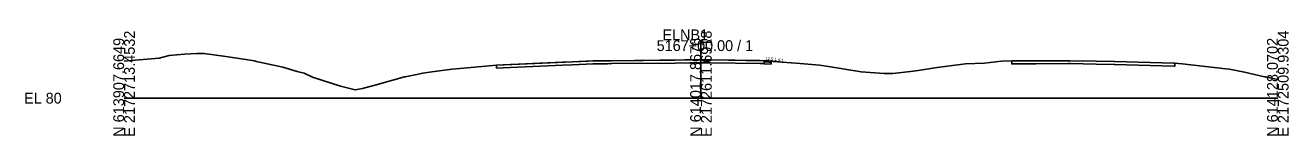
# Model space of a CAD drawing. Extents: x -26 to 1303, y -3010 to 12038.
# Drawn here: x -25.7 to 302.8, y -2509.7 to -2482.2 of the extents above; entities that cross this region are included whole.
import ezdxf

# ---------------------------------------------------------------- set-up
doc = ezdxf.new("R2010")
doc.units = 0
for name, color, linetype in [('RD_GPK_XS_Cell', 7, 'Continuous'), ('RD_XS_Base', 7, 'Continuous'), ('RD_XS_ExGround', 7, 'Continuous'), ('RD_XS_ExPaveRet', 7, 'Continuous'), ('RD_XS_Greenside', 7, 'Continuous'), ('RD_XS_Pave', 7, 'Continuous'), ('RD_XS_PaveOvlay_CP', 7, 'Continuous'), ('RD_XS_TieSlope', 7, 'Continuous'), ('RD_XS_TX_ShdSlope', 7, 'Continuous'), ('RD_XS_TX_Slope', 7, 'Continuous')]:
    doc.layers.add(name, color=color, linetype=linetype)

msp = doc.modelspace()

# ---------------------------------------------------------------- linework, layer by layer
at = {"layer": 'RD_GPK_XS_Cell'}
for p, q in [((150, -2500), (150, -2485)), ((0, -2500), (150, -2500)), ((150, -2500), (300, -2500))]:
    msp.add_line(p, q, dxfattribs=at)
at = {"layer": 'RD_XS_Base'}
for p, q in [((167.76, -2490.68), (166.41, -2490.63)), ((166.41, -2491.13), (168.26, -2491.2)), ((168.26, -2490.7), (167.76, -2490.68)), ((167.76, -2490.68), (167.76, -2490.68)), ((168.26, -2491.2), (168.26, -2490.7)), ((168.26, -2490.7), (168.26, -2490.7))]:
    msp.add_line(p, q, dxfattribs=at)
at = {"layer": 'RD_XS_ExGround'}
msp.add_lwpolyline([(0, -2490.43), (1.84, -2490.25), (9.12, -2489.69), (11.74, -2488.96), (15.67, -2488.57), (18.92, -2488.46), (20.85, -2488.4), (26.43, -2489.18), (33.88, -2490.35), (34.35, -2490.5), (35.2, -2490.65), (41.3, -2491.98), (44.99, -2493.07), (46.82, -2493.51), (48.98, -2494.57), (56.29, -2496.86), (60.13, -2497.85), (61.96, -2497.47), (65.59, -2496.51), (72.95, -2494.52), (73.13, -2494.5), (75.71, -2493.94), (77.69, -2493.5), (80.02, -2493.18), (85.31, -2492.5), (88.29, -2492.25), (92.11, -2491.87), (96.85, -2491.45), (120.67, -2490.42), (122.42, -2490.36), (123.26, -2490.31), (124.4, -2490.35), (126.24, -2490.33), (145.78, -2490.12), (150.65, -2490.07), (152.45, -2490.1), (166.42, -2490.31), (175.78, -2491.07), (180.86, -2491.49), (183.16, -2491.8), (191.64, -2493.19), (195.18, -2493.41), (197.64, -2493.64), (198.46, -2493.61), (199.93, -2493.59), (204.53, -2493.12), (206.49, -2492.85), (211.43, -2492.08), (218.76, -2491.08), (223.77, -2490.9), (228.17, -2490.46), (230.82, -2490.37), (237.11, -2490.33), (245.76, -2490.31), (252.79, -2490.45), (257.64, -2490.54), (269.83, -2490.87), (273.24, -2490.96), (275.09, -2491.09), (286.46, -2492.39), (287.48, -2492.5), (291.38, -2493.24), (296.55, -2494.46), (296.78, -2494.51), (297.02, -2494.57), (300, -2495.17)], dxfattribs=at)
at = {"layer": 'RD_XS_ExPaveRet'}
for points in [[(165.36, -2490.29), (166.41, -2490.31), (166.41, -2490.44), (166.41, -2491.06), (165.36, -2491.04), (152.45, -2490.85), (150.85, -2490.82), (150.65, -2490.82), (150.11, -2490.82), (147.01, -2490.86), (143.27, -2490.9), (126.64, -2491.07), (126.38, -2491.08), (126.09, -2491.07), (125.69, -2491.08), (125.16, -2491.1), (121.98, -2491.1), (121.95, -2491.1), (121.93, -2491.1), (116.6, -2491.37), (113.99, -2491.46), (98.57, -2492.13), (96.85, -2492.2), (96.85, -2491.58), (96.85, -2491.45), (98.57, -2491.38), (113.99, -2490.71), (116.6, -2490.62), (121.93, -2490.35), (121.95, -2490.35), (121.98, -2490.35), (125.16, -2490.35), (125.69, -2490.33), (126.09, -2490.32), (126.38, -2490.33), (126.64, -2490.32), (143.27, -2490.15), (147.01, -2490.11), (150.11, -2490.07), (150.65, -2490.07), (150.85, -2490.07), (152.45, -2490.1), (165.36, -2490.29)], [(152.45, -2490.1), (150.85, -2490.07), (150.65, -2490.07), (150.11, -2490.07), (147.01, -2490.11), (143.27, -2490.15), (126.64, -2490.32), (126.38, -2490.33), (126.09, -2490.32), (125.69, -2490.33), (125.16, -2490.35), (121.98, -2490.35), (121.95, -2490.35), (121.93, -2490.35), (116.6, -2490.62), (113.99, -2490.71), (98.57, -2491.38), (96.85, -2491.45), (96.85, -2491.58), (96.85, -2492.2), (98.57, -2492.13), (113.99, -2491.46), (116.6, -2491.37), (121.93, -2491.1), (121.95, -2491.1), (121.98, -2491.1), (125.16, -2491.1), (125.69, -2491.08), (126.09, -2491.07), (126.38, -2491.08), (126.64, -2491.07), (143.27, -2490.9), (147.01, -2490.86), (150.11, -2490.82), (150.65, -2490.82), (150.85, -2490.82), (152.45, -2490.85), (165.36, -2491.04), (166.41, -2491.06), (166.41, -2490.44), (166.41, -2490.31), (165.36, -2490.29), (152.45, -2490.1)], [(273.24, -2490.96), (272.98, -2490.96), (269.83, -2490.87), (260.63, -2490.62), (257.64, -2490.54), (257.41, -2490.54), (252.79, -2490.45), (246, -2490.32), (245.86, -2490.32), (245.76, -2490.31), (245.75, -2490.31), (245.65, -2490.31), (245.53, -2490.31), (237.11, -2490.33), (231.27, -2490.37), (230.82, -2490.37), (230.82, -2490.82), (230.82, -2491.12), (231.27, -2491.12), (237.11, -2491.08), (245.53, -2491.06), (245.65, -2491.06), (245.75, -2491.06), (245.76, -2491.06), (245.86, -2491.07), (246, -2491.07), (252.79, -2491.2), (257.41, -2491.29), (257.64, -2491.29), (260.63, -2491.37), (269.83, -2491.62), (272.98, -2491.71), (273.24, -2491.71), (273.24, -2491.71), (273.24, -2491.71), (273.24, -2491.26), (273.24, -2490.96), (273.24, -2490.96), (273.24, -2490.96)], [(273.24, -2490.96), (272.98, -2490.96), (269.83, -2490.87), (260.63, -2490.62), (257.64, -2490.54), (257.41, -2490.54), (252.79, -2490.45), (246, -2490.32), (245.86, -2490.32), (245.76, -2490.31), (245.75, -2490.31), (245.65, -2490.31), (245.53, -2490.31), (237.11, -2490.33), (231.27, -2490.37), (230.82, -2490.37), (230.82, -2490.82), (230.82, -2491.12), (231.27, -2491.12), (237.11, -2491.08), (245.53, -2491.06), (245.65, -2491.06), (245.75, -2491.06), (245.76, -2491.06), (245.86, -2491.07), (246, -2491.07), (252.79, -2491.2), (257.41, -2491.29), (257.64, -2491.29), (260.63, -2491.37), (269.83, -2491.62), (272.98, -2491.71), (273.24, -2491.71), (273.24, -2491.71), (273.24, -2491.26), (273.24, -2490.96), (273.24, -2490.96)]]:
    msp.add_lwpolyline(points, dxfattribs=at)
at = {"layer": 'RD_XS_Greenside'}
msp.add_line((169.76, -2490.52), (170.41, -2490.63), dxfattribs=at)
at = {"layer": 'RD_XS_Pave'}
for p, q in [((167.76, -2490.36), (166.41, -2490.31)), ((167.76, -2490.52), (166.41, -2490.47)), ((166.41, -2490.47), (167.76, -2490.52)), ((166.41, -2490.63), (167.76, -2490.68)), ((167.76, -2490.52), (167.76, -2490.36)), ((167.76, -2490.36), (167.76, -2490.36)), ((167.76, -2490.68), (167.76, -2490.52)), ((167.76, -2490.52), (167.76, -2490.52))]:
    msp.add_line(p, q, dxfattribs=at)
at = {"layer": 'RD_XS_PaveOvlay_CP'}
msp.add_line((167.76, -2490.36), (166.41, -2490.31), dxfattribs=at)
at = {"layer": 'RD_XS_TieSlope'}
msp.add_line((167.76, -2490.36), (169.76, -2490.52), dxfattribs=at)

# ---------------------------------------------------------------- texts
at = {"layer": 'RD_GPK_XS_Cell'}
for s, p in [('E 2172713.4532', (2.8, -2510)), ('E 2172611.6918', (152.8, -2510)), ('E 2172509.9304', (302.8, -2510)), ('N 613907.6649', (0, -2510)), ('N 614017.8676', (150, -2510)), ('N 614128.0702', (300, -2510))]:
    msp.add_text(s, height=2.8, rotation=90, dxfattribs=at).set_placement(p)
for s, p in [('ELNB1', (140, -2485)), ('5167+00.00 / 1', (138.48, -2487.8)), ('EL 80', (-26, -2501.4))]:
    msp.add_text(s, height=2.8, dxfattribs=at).set_placement(p)
at = {"layer": 'RD_XS_TX_ShdSlope'}
msp.add_text('12.5:1', height=0.75, rotation=355.4261, dxfattribs=at).set_placement((166.74, -2490.05))
at = {"layer": 'RD_XS_TX_Slope'}
msp.add_text('6:1', height=0.75, rotation=350.5377, dxfattribs=at).set_placement((170.04, -2490.35))

doc.saveas('drawing.dxf')
